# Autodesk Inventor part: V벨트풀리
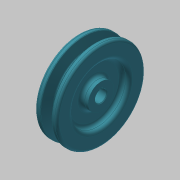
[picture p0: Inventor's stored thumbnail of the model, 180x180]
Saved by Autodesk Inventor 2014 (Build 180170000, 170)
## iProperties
Created: 2015-11
Part Number: V벨트풀리
Material: 강철, 탄소
Document SubType Name: Modeling
Designer: mduedu
Density: 1 g/cm^3
Appearance: 커뎃 파란색
Author: mduedu
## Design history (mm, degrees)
sketch "스케치1"
  geometry: L1 (-9.5, 0)-(9.5, 0); L2 (0, 0)-(0, 37.7); L3 (-4.825, 37.7)-(-9.5, 37.7); L4 (-9.5, 37.7)-(-9.5, 0); L5 (0, 28.7)-(-2.074, 28.7); L6 (-2.074, 28.7)-(-4.825, 37.7); L7 (4.825, 37.7)-(9.5, 37.7); L8 (9.5, 37.7)-(9.5, 0); L9 (0, 28.7)-(2.074, 28.7); L10 (2.074, 28.7)-(4.825, 37.7); L11 (-9.5, 35)-(9.5, 35); 3 further points
  constraints: 22 end point, 7 point on line, 4 perpendicular, 3 symmetric about line, 1 coincident, 1 horizontal, 1 horizontal alignment, 1 midpoint, 1 vertical
  dimensions: "d0" = 19 distance of L1.start L1.end; "d2" = 75.4 diameter of L2.end L1 (derived); "d3" = 34 deg angle of L10 L6; "d4" = 6.3 distance between parallel lines of L11 L9; "d5" = 2.7 distance between parallel lines of L7 L11; "d6" = 8 distance of point (4, 35) point (-4, 35); "d7" = 70 diameter of L11 L1
revolve "회전1" sketch "스케치1" stored, may be unused: angle "d8" = 90 deg
sketch "스케치2"
  geometry: C1 r 24 at (0, 0); C2 r 11 at (0, 0); 1 further point
  constraints: 2 centre point, 2 coincident
  dimensions: "d9" = 48 diameter of C1; "d10" = 22 diameter of C2
extrude "돌출1" cut sketch "스케치2" distance "d11" = 6; taper "d12" = 0 deg
fillet "모깎기1" dims "d13" = 3
fillet "모깎기2" dims "d14" = 3
fillet "모깎기3" dims "d15" = 1, "d16" = 0.5, "d17" = 2
hole "구멍1" diameter "d20" = 10; stored, may be unused: countersink angle "d24" = 90 deg, drill point angle "d26" = 118 deg; dims "d18" = 10, "d19" = 10, "d21" = 6, "d22" = 4, "d23" = 2, "d25" = 8
sketch "스케치3"
  geometry: L1 (-1.5, 0)-(1.5, 0); L2 (1.5, 0)-(1.5, 6.4); L3 (1.5, 6.4)-(-1.5, 6.4); L4 (-1.5, 6.4)-(-1.5, 0); 2 further points
  constraints: 8 end point, 2 parallel, 1 coincident, 1 horizontal, 1 midpoint, 1 perpendicular
  dimensions: "d27" = 3 distance of L2.end L3.end; "d29" = 6.4 distance of L3.end L1.start
extrude "돌출2" cut sketch "스케치3" stored distance "d30" = 6; taper "d31" = 0 deg
chamfer "모따기1" distance "d32" = 0.5; stored, may be unused: second distance "d33" = 2, angle "d34" = 45 deg
node "솔리드1"
mirror "대칭1"
